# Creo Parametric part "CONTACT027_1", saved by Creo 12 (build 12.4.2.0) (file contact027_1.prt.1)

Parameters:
  PTC_WM_ITERATION = "0"
  PTC_WM_VERSION = "-.0"
  PTC_WM_LIFECYCLE_STATE = "In Work"
  PTC_WM_LIFECYCLE = "MO_CADDocument"
  PTC_WM_CREATED_BY = "Maximilian Roepper (Z0017RMS: MO)"
  PTC_WM_CREATED_ON = "18-Sep-26 11:36:42 AM"
  PTC_WM_MODIFIED_BY = "Maximilian Roepper (Z0017RMS: MO)"
  PTC_WM_MODIFIED_ON = "18-Sep-26 11:36:46 AM"
  PDMLINKNUMBER = "PDM000071455276"
  PTC_WM_NAME = "contact027_1.prt"
  PTC_WM_NUMBER = "PDM000071455276"

Other parameters: WEIGHT, WEIGHT_FACTOR, WEIGHT_ADD, _MASS_TEMP, _DIFF_TEMP, MC_ERRORS, SUPPLIER

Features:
  1. coordinate system
  2. datum plane "PRT_YZ"
  3. datum plane "PRT_XY"
  4. datum plane "PRT_XZ"
  5. coordinate system
  6. datum axis
  7. datum axis
  8. datum axis
  9. coordinate system
  10. imported feature

Other named items: PRT, SIEMENS_MO, DRW_VIEW_ORG, PRT_X, PRT_Y, PRT_Z, CS0, ROUGH_GROB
